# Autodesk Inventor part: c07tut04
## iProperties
Shininess: 77.0
Length Units: 11269
Angle Units: 11279
Time Units: 11290
Mass Units: 11283
Length Display Precision: 3
Angle Display Precision: 2
Created: 2002-01
Part Number: c07tut04
Document SubType Name: Modeling
Designer: ***
Density: 0.0
Volumn: 0.0
Area: 0.0
PropertySet Name: Model Information
Control State: 0
Master: False
Checked Out: False
Author: ***
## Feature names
1. Extrusion1
2. Extrusion2
3. Hole1
4. Extrusion3
5. FaceDraft4
6. Fillet3
